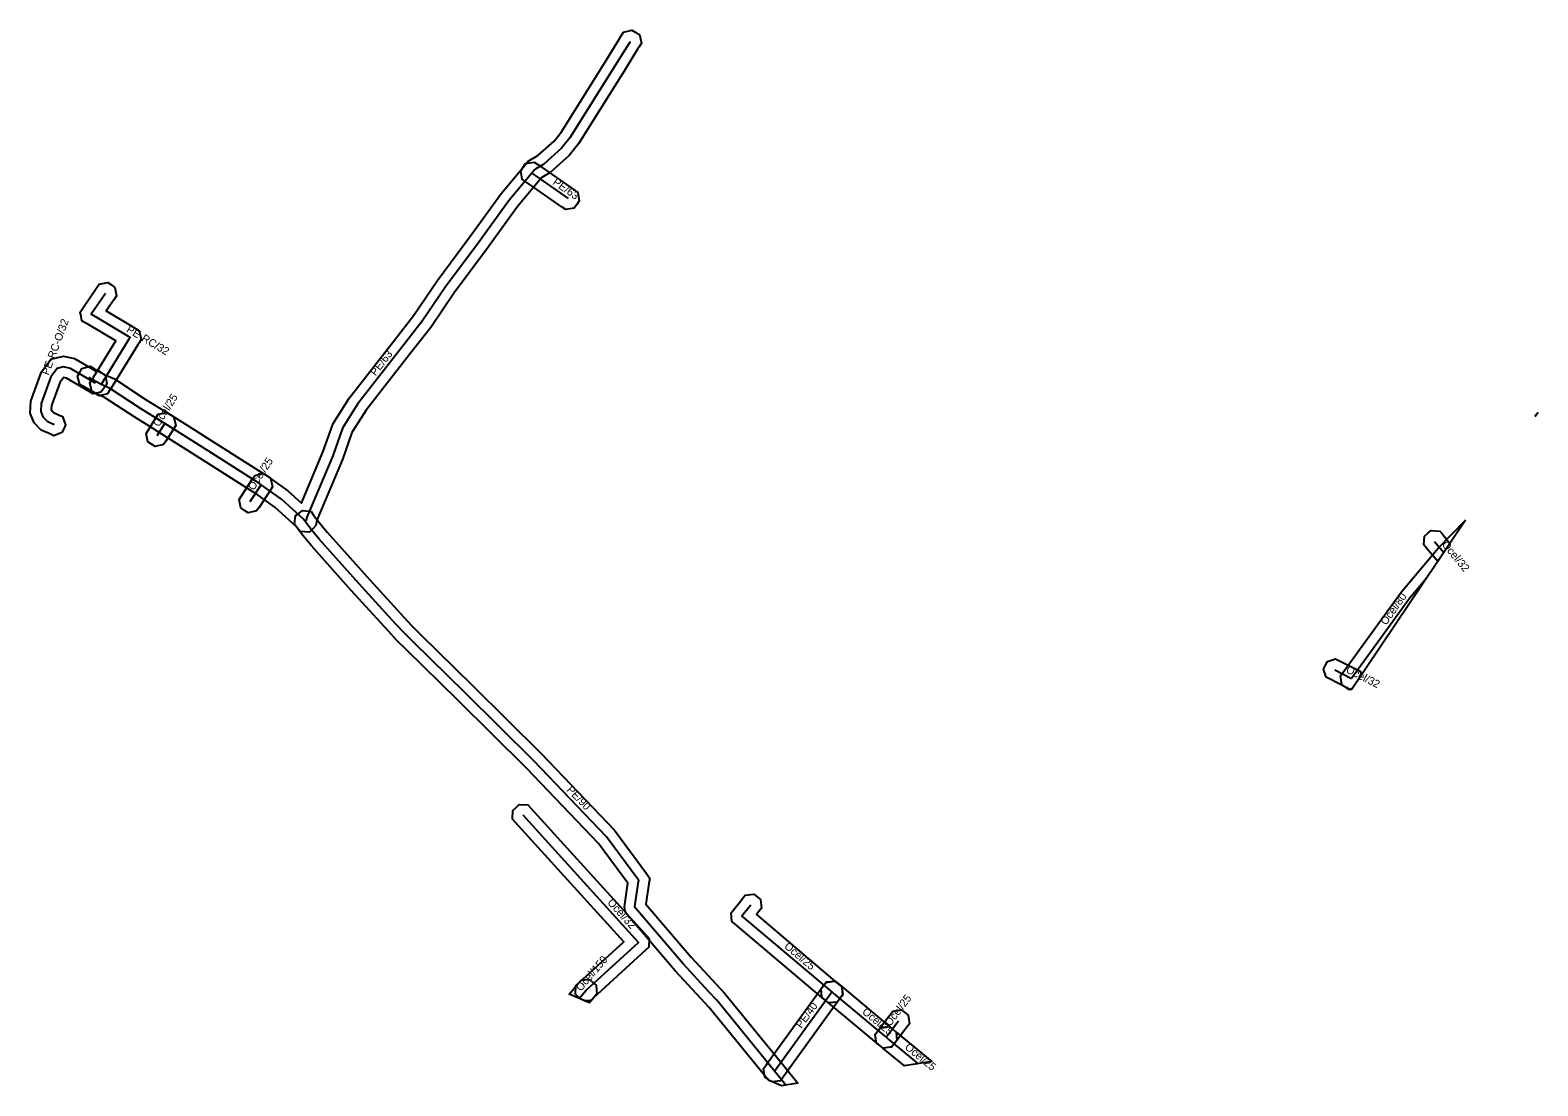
# Model space of a CAD drawing. Extents: x -600607 to -600238, y -1203924 to -1203617.
# Drawn here: x -600459 to -600314.7, y -1203923.9 to -1203822.9 of the extents above; entities that cross this region are included whole.
import ezdxf

# ---------------------------------------------------------------- set-up
doc = ezdxf.new("R2010")
doc.units = 0
for name, color, linetype in [('1', 7, 'Continuous'), ('14', 7, 'Continuous'), ('20', 7, 'Continuous'), ('24', 7, 'Continuous'), ('28', 7, 'Continuous'), ('30', 7, 'Continuous')]:
    doc.layers.add(name, color=color, linetype=linetype)

msp = doc.modelspace()

# ---------------------------------------------------------------- linework, layer by layer
at = {"layer": '1'}
for points in [[(-600434.32, -1203867), (-600433.03, -1203868.17), (-600430.97, -1203863.28), (-600429.99, -1203860.54), (-600428.47, -1203858.12), (-600424.04, -1203852.44), (-600422.27, -1203850.17), (-600420.05, -1203846.88), (-600416.93, -1203842.71), (-600413.89, -1203838.52), (-600411.75, -1203835.95), (-600411.35, -1203835.47), (-600411.1, -1203835.32), (-600410.4, -1203834.91), (-600408.85, -1203833.52), (-600408.15, -1203832.63), (-600403.84, -1203825.76), (-600402.55, -1203823.68), (-600402.41, -1203823.45), (-600402.19, -1203823.1), (-600401.39, -1203822.91), (-600401.03, -1203823.13), (-600400.68, -1203823.34), (-600400.49, -1203824.15), (-600400.71, -1203824.5), (-600400.85, -1203824.74), (-600402.14, -1203826.82), (-600406.51, -1203833.79), (-600407.39, -1203834.9), (-600409.22, -1203836.53), (-600410.03, -1203837.01), (-600410.21, -1203837.23), (-600412.31, -1203839.74), (-600415.32, -1203843.89), (-600418.42, -1203848.04), (-600420.65, -1203851.35), (-600422.46, -1203853.67), (-600426.83, -1203859.28), (-600428.19, -1203861.42), (-600429.11, -1203864), (-600431.55, -1203869.81), (-600431.65, -1203870.31), (-600431.95, -1203870.62), (-600432.27, -1203870.93), (-600432.71, -1203870.91), (-600433.16, -1203870.88), (-600433.44, -1203870.53), (-600433.55, -1203870.4), (-600435.58, -1203868.56), (-600437.41, -1203867.24), (-600437.58, -1203867.15), (-600442.5, -1203864.01), (-600444.32, -1203862.86), (-600446.65, -1203861.4), (-600447.28, -1203861), (-600448.98, -1203859.95), (-600451.87, -1203858.05), (-600452.65, -1203857.72), (-600453.21, -1203857.4), (-600453.88, -1203857.02), (-600454.24, -1203856.81), (-600454.46, -1203856.02), (-600454.26, -1203855.66), (-600454.05, -1203855.29), (-600453.26, -1203855.07), (-600452.9, -1203855.28), (-600452.23, -1203855.66), (-600451.77, -1203855.92), (-600450.93, -1203856.27), (-600447.9, -1203858.27), (-600446.22, -1203859.3), (-600445.59, -1203859.7), (-600443.26, -1203861.16), (-600441.42, -1203862.33), (-600436.54, -1203865.44), (-600436.33, -1203865.56)], [(-600410.75, -1203835.53), (-600410.41, -1203835.77), (-600406.93, -1203838.2), (-600406.58, -1203838.44), (-600406.44, -1203839.25), (-600406.68, -1203839.59), (-600406.91, -1203839.93), (-600407.73, -1203840.08), (-600408.07, -1203839.84), (-600411.55, -1203837.41), (-600411.89, -1203837.17), (-600412.04, -1203836.36), (-600411.8, -1203836.02), (-600411.57, -1203835.68)], [(-600450.97, -1203848.68), (-600451.72, -1203849.78), (-600449.11, -1203851.34), (-600448.92, -1203851.45), (-600448.56, -1203851.67), (-600448.46, -1203852.07), (-600448.36, -1203852.48), (-600448.58, -1203852.84), (-600448.69, -1203853.01), (-600451.24, -1203857.16), (-600451.36, -1203857.34), (-600451.58, -1203857.7), (-600452.38, -1203857.89), (-600452.73, -1203857.67), (-600453.09, -1203857.45), (-600453.28, -1203856.65), (-600453.06, -1203856.29), (-600452.95, -1203856.11), (-600450.81, -1203852.65), (-600453.49, -1203851.05), (-600453.66, -1203850.95), (-600454.04, -1203850.73), (-600454.13, -1203850.3), (-600454.22, -1203849.88), (-600453.97, -1203849.52), (-600452.61, -1203847.54), (-600452.38, -1203847.2), (-600451.57, -1203847.05), (-600451.22, -1203847.29), (-600450.88, -1203847.52), (-600450.73, -1203848.33)], [(-600454.77, -1203854.34), (-600452.74, -1203855.52), (-600452.47, -1203855.48), (-600452.13, -1203855.72), (-600451.8, -1203855.97), (-600451.67, -1203856.78), (-600451.91, -1203857.12), (-600451.99, -1203857.23), (-600452.22, -1203857.54), (-600452.97, -1203857.7), (-600453.3, -1203857.51), (-600455.52, -1203856.22), (-600455.8, -1203856.15), (-600455.82, -1203856.16), (-600456.12, -1203856.57), (-600456.96, -1203858.82), (-600456.98, -1203859.22), (-600456.93, -1203859.35), (-600456.78, -1203859.5), (-600456.29, -1203859.72), (-600455.91, -1203859.89), (-600455.62, -1203860.67), (-600455.79, -1203861.04), (-600455.96, -1203861.42), (-600456.74, -1203861.71), (-600457.11, -1203861.54), (-600457.94, -1203861.17), (-600458.63, -1203860.47), (-600459, -1203859.56), (-600458.94, -1203858.42), (-600457.9, -1203855.61), (-600457.02, -1203854.4), (-600455.82, -1203854.09)], [(-600447.91, -1203861.49), (-600447.68, -1203861.14), (-600446.96, -1203860.01), (-600446.74, -1203859.66), (-600445.93, -1203859.48), (-600445.58, -1203859.71), (-600445.23, -1203859.93), (-600445.05, -1203860.74), (-600445.28, -1203861.09), (-600446, -1203862.22), (-600446.22, -1203862.57), (-600447.03, -1203862.75), (-600447.38, -1203862.52), (-600447.73, -1203862.3)], [(-600314.89, -1203859.75), (-600314.67, -1203859.51), (-600314.88, -1203859.83)], [(-600438.99, -1203867.82), (-600438.77, -1203867.47), (-600437.71, -1203865.85), (-600437.48, -1203865.51), (-600436.67, -1203865.34), (-600436.32, -1203865.56), (-600435.98, -1203865.79), (-600435.81, -1203866.6), (-600436.03, -1203866.95), (-600437.09, -1203868.57), (-600437.32, -1203868.91), (-600438.13, -1203869.08), (-600438.48, -1203868.86), (-600438.82, -1203868.63)], [(-600387.07, -1203923.92), (-600388.32, -1203923.38), (-600388.52, -1203923.14), (-600394.02, -1203916.38), (-600394.79, -1203915.56), (-600397.21, -1203912.95), (-600397.24, -1203912.92), (-600401.88, -1203907.5), (-600402.04, -1203907.16), (-600402.11, -1203906.78), (-600401.79, -1203904.53), (-600404.59, -1203900.74), (-600411.5, -1203893.51), (-600418.05, -1203887.02), (-600423.02, -1203882.17), (-600423.9, -1203881.3), (-600424.71, -1203880.41), (-600428.26, -1203876.52), (-600432.08, -1203872.25), (-600432.88, -1203871.3), (-600433.46, -1203870.51), (-600433.71, -1203870.17), (-600433.59, -1203869.35), (-600433.26, -1203869.11), (-600432.92, -1203868.86), (-600432.1, -1203868.98), (-600431.86, -1203869.31), (-600431.3, -1203870.06), (-600430.56, -1203870.95), (-600426.78, -1203875.18), (-600423.24, -1203879.06), (-600422.46, -1203879.92), (-600421.62, -1203880.74), (-600416.65, -1203885.6), (-600410.08, -1203892.11), (-600403.05, -1203899.45), (-600400, -1203903.59), (-600399.67, -1203904.08), (-600399.78, -1203904.55), (-600400.06, -1203906.55), (-600395.73, -1203911.61), (-600395.73, -1203911.61), (-600393.33, -1203914.2), (-600392.52, -1203915.06), (-600386.96, -1203921.88), (-600385.51, -1203923.67)], [(-600321.58, -1203869.78), (-600332.45, -1203885.94), (-600332.76, -1203885.99), (-600333.1, -1203885.75), (-600333.43, -1203885.51), (-600333.56, -1203884.69), (-600333.32, -1203884.35), (-600327.76, -1203876.68), (-600324.21, -1203872.46)], [(-600323.09, -1203872.02), (-600324.25, -1203873.75), (-600325.32, -1203872.46), (-600325.58, -1203872.14), (-600325.51, -1203871.31), (-600325.19, -1203871.05), (-600324.87, -1203870.78), (-600324.04, -1203870.86), (-600323.78, -1203871.18)], [(-600331.56, -1203884.62), (-600332.48, -1203885.98), (-600332.59, -1203886.02), (-600332.96, -1203885.83), (-600334.56, -1203885.02), (-600334.93, -1203884.83), (-600335.19, -1203884.05), (-600335, -1203883.68), (-600334.82, -1203883.31), (-600334.03, -1203883.05), (-600333.66, -1203883.24), (-600332.06, -1203884.05), (-600331.69, -1203884.24)], [(-600405.92, -1203915.77), (-600406.41, -1203915.56), (-600406.51, -1203915.45), (-600406.79, -1203915.15), (-600406.75, -1203914.32), (-600406.44, -1203914.04), (-600402.16, -1203910.13), (-600412.56, -1203898.69), (-600412.84, -1203898.39), (-600412.8, -1203897.56), (-600412.49, -1203897.28), (-600412.19, -1203897), (-600411.36, -1203897.04), (-600411.08, -1203897.35), (-600400.01, -1203909.53), (-600399.73, -1203909.83), (-600399.77, -1203910.66), (-600400.08, -1203910.94), (-600405.1, -1203915.52), (-600405.4, -1203915.8)], [(-600388.98, -1203906.91), (-600389.23, -1203907.24), (-600389.42, -1203907.47), (-600389.47, -1203907.54), (-600381.73, -1203914.08), (-600381.62, -1203914.18), (-600381.3, -1203914.44), (-600381.23, -1203915.27), (-600381.49, -1203915.58), (-600381.76, -1203915.9), (-600382.59, -1203915.97), (-600382.9, -1203915.71), (-600383.02, -1203915.61), (-600391.51, -1203908.44), (-600391.82, -1203908.18), (-600391.9, -1203907.38), (-600391.64, -1203907.06), (-600390.98, -1203906.23), (-600390.81, -1203906), (-600390.55, -1203905.68), (-600389.73, -1203905.58), (-600389.4, -1203905.83), (-600389.08, -1203906.09)], [(-600405.01, -1203915.43), (-600405.47, -1203915.97), (-600407.39, -1203915.14), (-600406.53, -1203914.13), (-600406.26, -1203913.82), (-600405.44, -1203913.75), (-600405.12, -1203914.02), (-600404.81, -1203914.29), (-600404.74, -1203915.11)], [(-600387.92, -1203923.55), (-600388.13, -1203923.46), (-600388.32, -1203923.32), (-600388.66, -1203923.08), (-600388.79, -1203922.26), (-600388.55, -1203921.93), (-600388.32, -1203921.6), (-600383.39, -1203914.79), (-600383.07, -1203914.35), (-600382.83, -1203914.02), (-600382.01, -1203913.89), (-600381.67, -1203914.13), (-600381.34, -1203914.38), (-600381.21, -1203915.19), (-600381.45, -1203915.53), (-600381.77, -1203915.97), (-600386.7, -1203922.78), (-600386.93, -1203923.09), (-600387.17, -1203923.43)], [(-600381.94, -1203913.91), (-600381.62, -1203914.17), (-600381.5, -1203914.27), (-600376.9, -1203918.1), (-600376.42, -1203918.5), (-600376.1, -1203918.77), (-600376.03, -1203919.59), (-600376.29, -1203919.91), (-600376.56, -1203920.23), (-600377.38, -1203920.3), (-600377.7, -1203920.04), (-600378.18, -1203919.64), (-600382.78, -1203915.81), (-600382.9, -1203915.71), (-600383.22, -1203915.44), (-600383.29, -1203914.62), (-600383.03, -1203914.3), (-600382.76, -1203913.98)], [(-600378.11, -1203919), (-600377.86, -1203918.67), (-600376.85, -1203917.34), (-600376.68, -1203917.11), (-600376.43, -1203916.78), (-600375.61, -1203916.66), (-600375.28, -1203916.91), (-600374.95, -1203917.16), (-600374.83, -1203917.98), (-600375.08, -1203918.31), (-600375.26, -1203918.55), (-600376.26, -1203919.87), (-600376.51, -1203920.2), (-600377.33, -1203920.32), (-600377.66, -1203920.07), (-600377.99, -1203919.82)], [(-600376.09, -1203918.77), (-600372.68, -1203921.58), (-600375.31, -1203922.01), (-600377.36, -1203920.31), (-600377.69, -1203920.04), (-600378.01, -1203919.78), (-600378.1, -1203918.96), (-600377.83, -1203918.64), (-600377.57, -1203918.32), (-600376.75, -1203918.23), (-600376.43, -1203918.5)]]:
    msp.add_lwpolyline(points, close=True, dxfattribs=at)
at = {"layer": '14'}
for points in [[(-600324.55, -1203871.82), (-600323.67, -1203872.89)], [(-600325.29, -1203875.3), (-600326.97, -1203877.3), (-600332.51, -1203884.94)], [(-600334.11, -1203884.13), (-600332.51, -1203884.94)], [(-600405.77, -1203914.78), (-600400.75, -1203910.2), (-600411.82, -1203898.02)], [(-600406.43, -1203915.55), (-600405.77, -1203914.78)]]:
    msp.add_lwpolyline(points, dxfattribs=at)
at = {"layer": '24'}
for points in [[(-600401.56, -1203823.98), (-600401.7, -1203824.21), (-600402.99, -1203826.29), (-600407.33, -1203833.21), (-600408.12, -1203834.21), (-600409.81, -1203835.72), (-600410.59, -1203836.18), (-600410.69, -1203836.24), (-600410.98, -1203836.59), (-600413.1, -1203839.13), (-600416.12, -1203843.3), (-600419.23, -1203847.46), (-600421.46, -1203850.76), (-600423.25, -1203853.06), (-600427.65, -1203858.7), (-600429.09, -1203860.98), (-600430.04, -1203863.64), (-600432.51, -1203869.52), (-600432.57, -1203869.82), (-600432.66, -1203869.91), (-600432.82, -1203869.71), (-600434.95, -1203867.78), (-600436.87, -1203866.4), (-600437.06, -1203866.29), (-600441.96, -1203863.17), (-600443.79, -1203862.01), (-600446.12, -1203860.55), (-600446.75, -1203860.15), (-600448.44, -1203859.11), (-600451.4, -1203857.16), (-600452.21, -1203856.82), (-600452.72, -1203856.53), (-600453.39, -1203856.15)], [(-600451.79, -1203848.11), (-600453.15, -1203850.09), (-600452.98, -1203850.19), (-600449.62, -1203852.2), (-600449.43, -1203852.31), (-600449.54, -1203852.49), (-600452.1, -1203856.64), (-600452.21, -1203856.82)], [(-600452.72, -1203856.53), (-600452.8, -1203856.64), (-600455.14, -1203855.28), (-600455.81, -1203855.12), (-600456.42, -1203855.28), (-600457.01, -1203856.09), (-600457.95, -1203858.62), (-600457.99, -1203859.39), (-600457.78, -1203859.91), (-600457.36, -1203860.33), (-600456.7, -1203860.63)], [(-600446.84, -1203861.68), (-600446.12, -1203860.55)], [(-600437.93, -1203868.02), (-600436.87, -1203866.4)], [(-600386.65, -1203923.85), (-600387.74, -1203922.51), (-600393.27, -1203915.72), (-600394.06, -1203914.88), (-600396.47, -1203912.28), (-600396.48, -1203912.26), (-600401.03, -1203906.96), (-600401.08, -1203906.85), (-600401.1, -1203906.75), (-600400.76, -1203904.37), (-600400.74, -1203904.28), (-600400.82, -1203904.16), (-600403.82, -1203900.09), (-600410.79, -1203892.81), (-600417.35, -1203886.31), (-600422.32, -1203881.45), (-600423.18, -1203880.61), (-600423.98, -1203879.74), (-600427.52, -1203875.85), (-600431.32, -1203871.6), (-600432.09, -1203870.68), (-600432.66, -1203869.91)], [(-600390.02, -1203906.62), (-600390.2, -1203906.85), (-600390.86, -1203907.68), (-600382.37, -1203914.84), (-600382.26, -1203914.94)], [(-600387.74, -1203922.51), (-600387.51, -1203922.19), (-600382.58, -1203915.38), (-600382.26, -1203914.94)], [(-600382.26, -1203914.94), (-600382.14, -1203915.04), (-600377.54, -1203918.87), (-600377.06, -1203919.27)], [(-600377.06, -1203919.27), (-600376.06, -1203917.94), (-600375.88, -1203917.71)], [(-600377.06, -1203919.27), (-600376.73, -1203919.54), (-600373.99, -1203921.8)]]:
    msp.add_lwpolyline(points, dxfattribs=at)
at = {"layer": '28'}
msp.add_lwpolyline([(-600410.98, -1203836.59), (-600407.5, -1203839.02)], dxfattribs=at)

# ---------------------------------------------------------------- texts
at = {"layer": '20'}
for s, rotation, p in [('Ocel/32', 309.5031, (-600323.91, -1203872.15)), ('Ocel/80', 54.053, (-600329.2, -1203879.9)), ('Ocel/32', 333.1492, (-600333.11, -1203884.33)), ('Ocel/32', 312.2667, (-600403.8, -1203906.42)), ('Ocel/150', 49.6001, (-600406.27, -1203914.93))]:
    msp.add_text(s, height=0.75, rotation=rotation, dxfattribs=at).set_placement(p)
at = {"layer": '30'}
for s, rotation, p in [('PE/63', 325.0908, (-600409.04, -1203837.61)), ('PE-RC-O/32', 69.6179, (-600457.24, -1203855.98)), ('PE-RC/32', 329.1443, (-600449.85, -1203851.74)), ('PE/63', 52.0618, (-600425.94, -1203856.05)), ('Ocel/25', 57.496, (-600446.68, -1203860.92)), ('Ocel/25', 56.8024, (-600437.6, -1203867.01)), ('PE/90', 313.7538, (-600407.69, -1203895.64)), ('Ocel/25', 319.8285, (-600386.88, -1203910.67)), ('Ocel/25', 52.8891, (-600376.67, -1203918.29)), ('PE/40', 54.0979, (-600385.17, -1203918.48)), ('Ocel/25', 320.2189, (-600379.42, -1203916.94)), ('Ocel/25', 320.505, (-600375.33, -1203920.33))]:
    msp.add_text(s, height=0.75, rotation=rotation, dxfattribs=at).set_placement(p)

doc.saveas('drawing.dxf')
